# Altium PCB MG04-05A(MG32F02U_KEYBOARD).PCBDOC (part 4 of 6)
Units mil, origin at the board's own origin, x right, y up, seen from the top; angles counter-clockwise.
Board outline 17912.8 x 10422.68 mil, 2 copper layers (Top Layer, Bottom Layer); 623 components, 347 nets, 1816 pads, 821 vias.
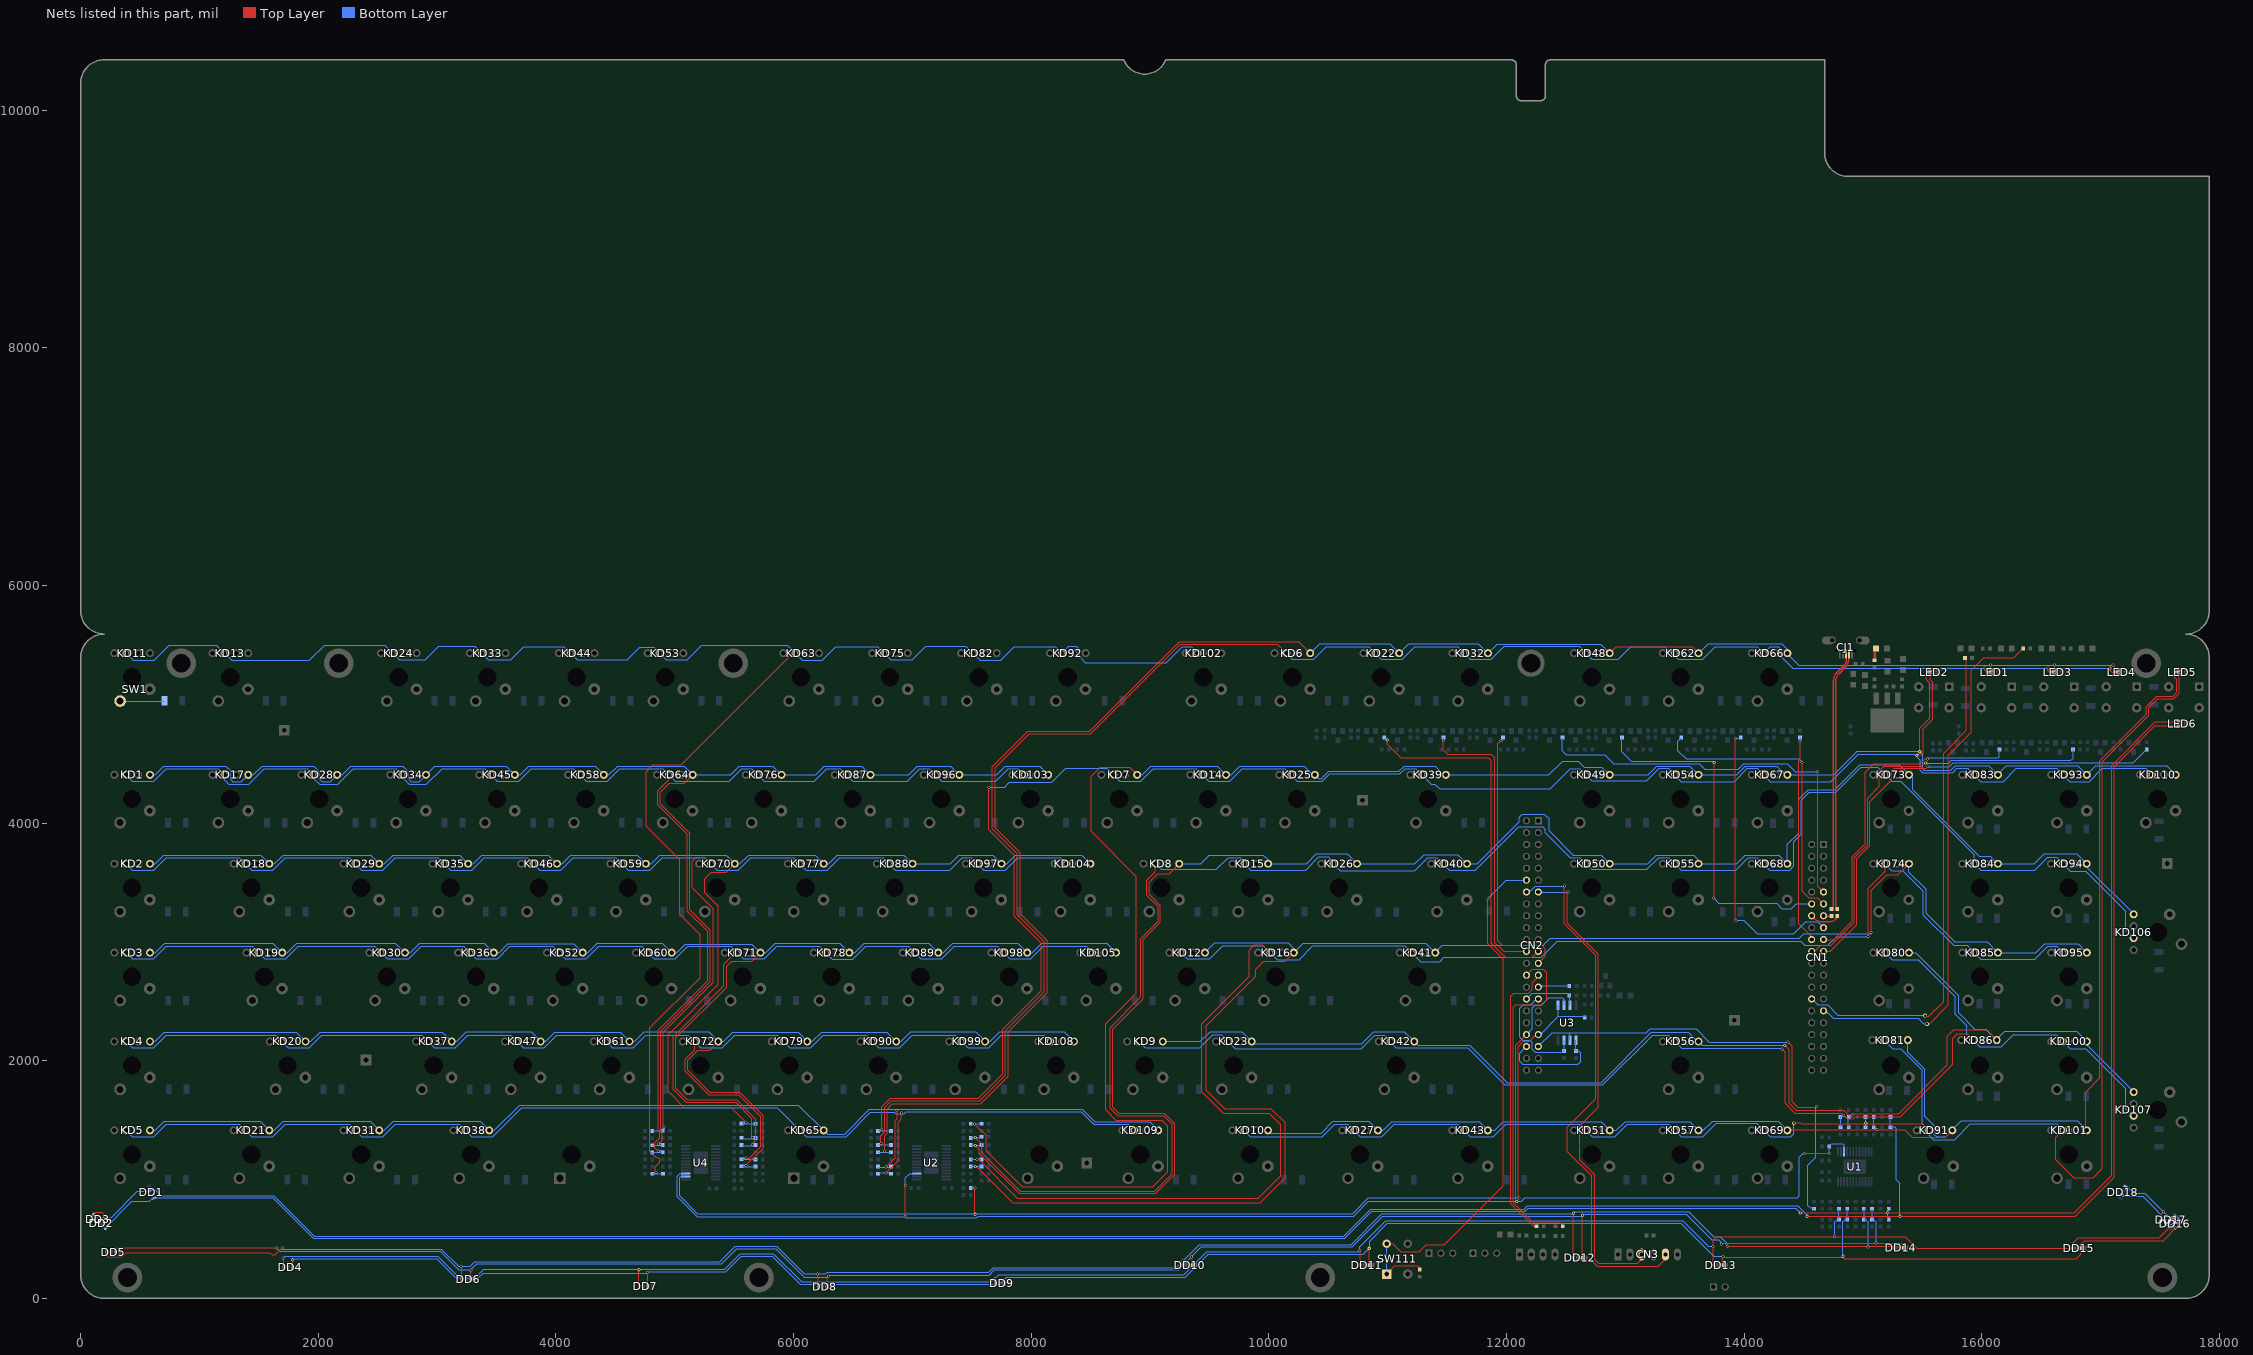
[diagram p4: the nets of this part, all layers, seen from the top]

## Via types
v1: diameter 30, hole 12, Top Layer to Bottom Layer, tented both sides, 273 vias
v2: diameter 26, hole 16, Top Layer to Bottom Layer, tented both sides, 181 vias
v3: diameter 26, hole 12, Top Layer to Bottom Layer, tented both sides, 165 vias
v4: diameter 33, hole 20, Top Layer to Bottom Layer, tented both sides, 61 vias
v5: diameter 25, hole 12, Top Layer to Bottom Layer, tented both sides, 47 vias
v6: diameter 20, hole 12, Top Layer to Bottom Layer, tented both sides, 40 vias
v7: diameter 30, hole 16, Top Layer to Bottom Layer, tented both sides, 30 vias
v8: diameter 28, hole 16, Top Layer to Bottom Layer, tented both sides, 12 vias
v9: diameter 35, hole 20, Top Layer to Bottom Layer, tented both sides, 5 vias
v10: diameter 25, hole 16, Top Layer to Bottom Layer, tented both sides, 3 vias
v11: diameter 40, hole 12, Top Layer to Bottom Layer, tented both sides, 3 vias
v12: diameter 40, hole 20, Top Layer to Bottom Layer, tented both sides, 1 vias

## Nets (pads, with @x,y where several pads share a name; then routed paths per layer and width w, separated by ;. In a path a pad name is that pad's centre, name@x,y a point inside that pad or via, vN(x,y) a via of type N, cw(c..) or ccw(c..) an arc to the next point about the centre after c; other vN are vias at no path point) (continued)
LED_G1: C51.1 KD1.3 KD17.3 KD28.3 KD34.3 KD45.3 KD58.3 KD64.3 KD76.3 KD87.3 KD96.3 KD103.3 R121.1 | length 12173.4
  Top Layer w8: v2(4862.07,1298.92) 4892.57,1329.41 4892.57,1408.92 4882.32,1419.16 4882.32,2249.07 5296.96,2663.71 5296.96,3097.04 5125,3269 5125,3915.41 4878.66,4161.75 4878.66,4261.31 4951.45,4334.1 5078.06,4334.1 KD64.3@5150.17,4406.2
  Bottom Layer w8: KD1.3@583.27,4406.2 627.01,4406.2 699.21,4478.4 1221.77,4478.4 1261.77,4438.4 1261.77,4367.8 1281.77,4347.8 1351.76,4347.8 KD17.3@1410.16,4406.2 1453.9,4406.2 1526.1,4478.4 1961.17,4478.4 2006.77,4432.8 2006.77,4372.8 2031.77,4347.8 2099.64,4347.8 KD28.3@2158.04,4406.2 2201.78,4406.2 2273.98,4478.4 2711.17,4478.4 2756.77,4432.8 2756.77,4372.8 2781.77,4347.8 2847.75,4347.8 KD34.3@2906.15,4406.2 2978.35,4478.4 3581.95,4478.4 KD45.3@3654.14,4406.2 3697.89,4406.2 3770.09,4478.4 4329.98,4478.4 KD58.3@4402.18,4406.2 4445.92,4406.2 4518.12,4478.4 5077.97,4478.4 KD64.3@5150.17,4406.2 5470.2,4406.2 5542.4,4478.4 5826,4478.4 KD76.3@5898.2,4406.2 6185.2,4406.2 6257.4,4478.4 6574.04,4478.4 KD87.3@6646.24,4406.2 6968.2,4406.2 7040.4,4478.4 7322.12,4478.4 KD96.3@7394.31,4406.2 7710.2,4406.2 7782.4,4478.4 8070.11,4478.4 KD103.3@8142.3,4406.2 ; C51.1@4812,1290.31 R121.1@4896,1290.31
  Bottom Layer w12: v2@4867.43,1301.08 R121.1@4887.13,1301.08
LED_G2: C57.1 KD2.3 KD18.3 KD29.3 KD35.3 KD46.3 KD59.3 KD70.3 KD77.3 KD88.3 KD97.3 KD104.3 R126.2 | length 11735.7
  Top Layer w8: KD70.3@5504.58,3657.8 5432.47,3585.7 5305.86,3585.7 5252,3531.84 5252,3414 5366.96,3299.04 5366.96,2643.71 4943.54,2220.29 4943.54,1741.47 5077.28,1607.72 5471.82,1607.72 v2(5598.15,1481.39)
  Bottom Layer w8: KD2.3@583.27,3657.8 627.01,3657.8 699.21,3730 1515.01,3730 KD18.3@1587.21,3657.8 1630.95,3657.8 1703.15,3730 2440.4,3730 KD29.3@2512.6,3657.8 2556.35,3657.8 2628.54,3730 3188.29,3730 KD35.3@3260.48,3657.8 3304.23,3657.8 3376.42,3730 3936.32,3730 KD46.3@4008.51,3657.8 4052.26,3657.8 4124.46,3730 4684.31,3730 KD59.3@4756.51,3657.8 4800.25,3657.8 4872.45,3730 5432.38,3730 KD70.3@5504.58,3657.8 5548.32,3657.8 5620.52,3730 6180.37,3730 KD77.3@6252.57,3657.8 6296.32,3657.8 6368.51,3730 6928.45,3730 KD88.3@7000.64,3657.8 7317.8,3657.8 7390,3730 7676.49,3730 KD97.3@7748.68,3657.8 7792.43,3657.8 7864.63,3730 8424.52,3730 KD104.3@8496.72,3657.8 ; R126.2@5563.58,1471.39 C57.1@5687.58,1471.39
  Bottom Layer w12: R126.2@5572.87,1478.92 v2@5592.57,1478.92
LED_G3: C52.1 KD3.3 KD19.3 KD30.3 KD36.3 KD52.3 KD60.3 KD71.3 KD78.3 KD89.3 KD98.3 KD105.3 R120.2 | length 11446
  Top Layer w8: 5648,2837.4 5648.7,2838.1 ; v2@5648.79,1296.17 5683.15,1330.53 5683.15,1495 ; 5649.01,2838.1 5648.7,2838.1 ; 5683.15,1505 5683.15,1495 ; KD71.3@5720.1,2909.5 5648.7,2838.1 ; 5648.7,2838.1 5478.25,2838.1 5435,2794.85 5435,2620.6 5007.32,2192.92 5007.32,1767.68 5103.64,1671.36 5520.79,1671.36 5683.15,1509 5683.15,1495
  Bottom Layer w8: KD3.3@583.27,2910.2 627.01,2910.2 706.81,2990 1615.68,2990 KD19.3@1695.48,2910.2 1739.22,2910.2 1819.02,2990 2649.14,2990 KD30.3@2728.94,2910.2 2772.69,2910.2 2852.48,2990 3397.22,2990 KD36.3@3477.01,2910.2 3520.76,2910.2 3595.55,2985 4150.25,2985 KD52.3@4225.04,2910.2 4268.79,2910.2 4348.59,2990 4893.29,2990 KD60.3@4973.09,2910.2 5016.83,2910.2 5089.03,2982.4 5648.92,2982.4 KD71.3@5721.12,2910.2 5764.86,2910.2 5844.66,2990 6389.35,2990 KD78.3@6469.15,2910.2 6512.9,2910.2 6592.69,2990 7137.39,2990 KD89.3@7217.18,2910.2 7260.93,2910.2 7340.72,2990 7885.42,2990 KD98.3@7965.21,2910.2 8008.96,2910.2 8088.76,2990 8633.41,2990 KD105.3@8713.21,2910.2 ; R120.2@5563.58,1291.39 5569.97,1285 C52.1@5668.15,1285
  other v2: 5653.15,1295
LED_G4: C45.1 KD4.3 KD20.3 KD37.3 KD47.3 KD61.3 KD72.3 KD79.3 KD90.3 KD99.3 KD108.3 R114.2 | length 10183
  Top Layer w8: KD72.3@5366.76,2162.1 5294.65,2090 5193.79,2090 5109.6,2005.81 5109.6,1918.4 5293,1735 5547.15,1735 5743.15,1539 5743.15,1265 v2(5598.15,1120)
  Bottom Layer w8: KD4.3@583.27,2162.1 627.01,2162.1 704.91,2240 1814.43,2240 KD20.3@1892.33,2162.1 1936.07,2162.1 2014.97,2241 3043.76,2241 KD37.3@3122.65,2162.1 3166.4,2162.1 3246.29,2242 3790.82,2242 KD47.3@3870.71,2162.1 3914.46,2162.1 3991.36,2239 4541.83,2239 KD61.3@4618.73,2162.1 4662.47,2162.1 4742.37,2242 5286.86,2242 KD72.3@5366.76,2162.1 5410.5,2162.1 5488.4,2240 6036.89,2240 KD79.3@6114.79,2162.1 6158.53,2162.1 6236.43,2240 6784.92,2240 KD90.3@6862.82,2162.1 6906.57,2162.1 6986.46,2242 7530.96,2242 KD99.3@7610.85,2162.1 7654.6,2162.1 7734.5,2242 8279,2242 KD108.3@8358.9,2162.1 ; R114.2@5564.97,1110 C45.1@5686.19,1110
  Bottom Layer w12: R114.2@5572.87,1118.92 v2@5592.57,1118.92
LED_G5: C28.1 KD5.3 KD21.3 KD31.3 KD38.3 KD65.3 KD109.3 R91.1 | length 9634.9
  Top Layer w8: v2(6778.24,1106) 6857,1184.76 6857,1493 6874,1510 v2@6874,1579.47
  Bottom Layer w8: KD5.3@583.27,1414.1 627.01,1414.1 702.71,1489.8 1511.52,1489.8 KD21.3@1587.22,1414.1 1630.96,1414.1 1706.66,1489.8 2436.72,1489.8 KD31.3@2512.42,1414.1 2556.17,1414.1 2631.87,1489.8 3361.92,1489.8 KD38.3@3437.62,1414.1 3481.37,1414.1 3694.23,1626.97 6039.73,1626.97 KD65.3@6252.59,1414.1 6285.51,1381.19 6428.19,1381.19 6637,1590 8428.47,1590 8532.17,1486.3 8995.36,1486.3 KD109.3@9067.56,1414.1 ; C28.1@6715,1104.89 R91.1@6815,1104.89
  other v2: 6871,1581.47
LED_G6: C34.1 KD6.3 KD22.3 KD32.3 KD48.3 KD62.3 KD66.3 LED1.3 LED3.3 LED4.3 R97.1 | length 14903.3
  Top Layer w8: v2(6735,1304.89) 6735,1369.89 6767,1401.89 6767,1607.47 6821.25,1661.72 7564.87,1661.72 7782.5,1879.35 7782.5,2254.35 8108.9,2580.75 8108.9,2999.56 7881.75,3226.72 7881.75,3741.72 7670.56,3952.9 7670.56,4475.03 7970.53,4775 8492.99,4775 9245.42,5527.43 10249.45,5527.43 KD6.3@10347.07,5429.8 ; KD48.3@12866.92,5429.8 12921.1,5483.98 13560.62,5483.98 KD62.3@13614.8,5429.8 ; v2(16072,5330) 16072,5290 LED1.3@16075.27,5286.73 ; LED3.3@16605.5,5286.73 16605.27,5286.73 16612,5280 v2(16612,5330) ; v2(17102,5330) 17145.27,5286.73 LED4.3@17145.5,5286.73
  Bottom Layer w8: C34.1@6710,1291.39 R97.1@6812.17,1291.39 ; KD6.3@10347.23,5429.8 10427.43,5510 11015.07,5510 KD22.3@11095.21,5429.86 ; KD22.3@11095.15,5429.8 KD22.3@11095.21,5429.86 ; KD22.3@11095.26,5429.8 KD22.3@11095.21,5429.86 ; KD48.3@12866.92,5429.8 12790.47,5506.25 11919.63,5506.25 KD32.3@11843.18,5429.8 11762.99,5510 11175.35,5510 KD22.3@11095.21,5429.86 ; KD62.3@13614.88,5429.88 13614.96,5429.8 13695.16,5510 14317.15,5510 14362.99,5464.16 KD66.3@14362.99,5429.8 14362.99,5426.01 14459,5330 v2(16072,5330) v2(16612,5330) v2(17102,5330)
LED_G7: C40.1 KD7.3 KD14.3 KD25.3 KD39.3 KD49.3 KD54.3 KD67.3 KD83.3 KD93.3 KD110.3 LED2.3 R106.2 | length 16841.8
  Top Layer w8: v2@7523.1,1466 v2@7525.78,1466 ; v2(7523.29,1468.48) v2@7525.78,1466 ; v2@7530.82,1466 v2@7525.78,1466 ; KD7.3@8890.38,4406.2 8826.58,4470 8578.15,4470 8503.15,4395 8503.15,3930.32 8884.85,3548.62 8884.85,2569.32 8627,2311.47 8627,1585.86 8711.86,1501 9096.85,1501 9150,1447.85 9150,1066.85 9023.63,940.48 7922.6,940.48 7620.29,1242.79 7620.29,1371.48 v2@7525.78,1466 ; v2@15476.85,4610.7 15476.85,4798.48 15562.45,4884.09 15562.45,5175.09 15529.6,5207.95 15529.6,5266.73 LED2.3@15549.6,5286.73
  Bottom Layer w8: R106.2@7489.17,1471.39 C40.1@7573.17,1471.39 ; KD7.3@8890.38,4406.2 8934.12,4406.2 9006.32,4478.4 9566.17,4478.4 ; 9566.25,4478.4 KD14.3@9638.45,4406.2 9682.19,4406.2 9754.39,4478.4 10296.17,4478.4 10368.37,4406.2 KD25.3@10386.44,4406.2 10417.64,4375 10441.15,4375 10501.85,4435.7 11093.85,4435.7 11136.55,4478.4 11400.75,4478.4 11472.95,4406.2 KD39.3@11488.88,4406.2 12355.17,4406.2 12470.43,4521.47 12601.08,4521.47 12651.85,4470.7 12802.27,4470.7 KD49.3@12866.77,4406.2 13190.8,4406.2 13264.6,4480 13541.04,4480 KD54.3@13614.84,4406.2 13936.01,4406.2 14009.81,4480 14273.15,4480 14346.95,4406.2 KD67.3@14362.87,4406.2 14754.35,4406.2 14952.63,4604.48 v2@15476.85,4604.48 ; v2@15481.85,4600.7 v2(15476.85,4600.7) 15501.85,4575.7 15501.85,4455.7 15511.85,4445.7 15736.85,4445.7 15774.64,4483.48 16057.43,4483.48 KD83.3@16134.7,4406.2 16134.7,4411.55 16206.63,4483.48 16805.25,4483.48 KD93.3@16882.53,4406.2 16959.81,4483.48 17553.31,4483.48 KD110.3@17630.59,4406.2
LED_G8: C33.1 KD8.3 KD15.3 KD26.3 KD40.3 KD50.3 KD55.3 KD68.3 KD73.3 KD84.3 KD94.3 KD106.3 R96.2 | length 15517.5
  Top Layer w8: v2@7523.1,1286 v2@7528.29,1286 ; v2(7528.29,1288.48) 7563.29,1253.48 7563.29,1219.18 7898.99,883.48 9047.24,883.48 9207,1043.24 9207,1471.46 9120.46,1558 8735.47,1558 8684,1609.47 8684,2263.47 8941.85,2521.32 8941.85,3020.7 9086.85,3165.7 9086.85,3305.7 8991.85,3400.7 8991.85,3503.7 9063.15,3575 9161.94,3575 KD8.3@9244.75,3657.8
  Bottom Layer w8: R96.2@7489.17,1290 7563.15,1290 ; KD8.3@9244.75,3657.8 9426.8,3657.8 9499,3730 9953.15,3730 9992.78,3690.37 KD15.3@9992.78,3657.8 10317.8,3657.8 10400,3740 10658.61,3740 KD26.3@10740.81,3657.8 11227.8,3657.8 11305,3735 11588.78,3735 KD40.3@11665.97,3657.8 11754.8,3657.8 12107,4010 12107,4050 12132,4075 12317,4075 12357,4035 12357,3935 12562,3730 12794.57,3730 KD50.3@12866.77,3657.8 13188.8,3657.8 13261,3730 13573.15,3730 13614.84,3688.31 KD55.3@13614.84,3657.8 13937.8,3657.8 14010,3730 14290.67,3730 KD68.3@14362.87,3657.8 14362.87,3820.87 14457,3915 14457,4200 14537,4280 14762,4280 14972,4490 15302.66,4490 KD73.3@15386.45,4406.2 15416.85,4375.81 15416.85,4280.7 15976.73,3720.81 16071.51,3720.81 KD84.3@16134.52,3657.8 16441.59,3657.8 16525.25,3741.47 16798.08,3741.47 16807.95,3731.6 ; 16808.55,3731.6 16807.95,3731.6 ; KD94.3@16878.15,3630 KD94.3@16881.75,3630 ; KD106.3@17275.69,3235.07 16881.75,3629.01 KD94.3@16881.75,3630 ; 16807.95,3731.6 KD94.3@16881.75,3657.8 KD94.3@16881.75,3630
LED_G9: C27.1 KD12.3 KD16.3 KD41.3 KD74.3 KD85.3 KD95.3 R89.2 | length 14364.5
  Top Layer w8: v2(7528.29,1111.39) 7538.5,1111.39 7843.29,806.6 9925.98,806.6 10135.15,1015.77 10135.15,1478.61 10016.76,1597 9630,1597 9474,1753 9474,2295.13 9889.6,2710.73 9889.6,2771.45 9956.25,2838.1 10137.22,2838.1 KD16.3@10209.32,2910.2 ; v2@15067,3070 v2(15067,3080) 15067,3435 15197.05,3565.05 15292.91,3565.05 KD74.3@15385.67,3657.8
  Bottom Layer w8: R89.2@7489.17,1111.39 v2(7528.29,1111.39) C27.1@7580,1111.39 ; KD12.3@9461.29,2931.86 KD12.3@9461.29,2910.2 9542.08,2991 10162.15,2991 10209.32,2943.83 KD16.3@10209.32,2910.2 10289.12,2990 11320.47,2990 KD41.3@11400.26,2910.2 11460.06,2970 12307,2970 12367,3030 14462,3030 14502,3070 v2@15067,3070 ; KD74.3@15385.67,3657.8 15385.67,3587.48 15531.77,3441.38 15531.77,3241.38 15773.15,3000 16044.91,3000 KD85.3@16134.7,2910.2 16453.99,2910.2 16527.79,2984 16808.95,2984 KD95.3@16882.75,2910.2
LED_G10: C11.1 KD9.3 KD23.3 KD42.3 KD56.3 KD80.3 KD86.3 KD100.3 KD107.3 R69.1 | length 11162.1
  Top Layer w8: v2(14340.26,2129.31) 14378.04,2091.53 14378.04,1643.74 14436.78,1585 14836.78,1585 14876.78,1545 v2(14905.59,1545) 14915.59,1555 15298.15,1555 15707.91,1964.76 15707.91,2205 15762.91,2260 16038.8,2260 KD86.3@16124.68,2174.11
  Bottom Layer w8: KD9.3@9106.93,2162.1 9423.26,2162.1 9506.15,2245 9772.06,2245 KD23.3@9854.96,2162.1 9872.06,2145 10781.15,2145 10881.85,2245.7 11139.48,2245.7 KD42.3@11223.07,2162.1 11253.71,2131.47 11688.27,2131.47 12003.27,1816.47 12795.47,1816.47 13218,2239 13527.92,2239 13604.82,2162.1 KD56.3@13614.81,2162.1 13646.91,2130 v2@14328.57,2130 ; C11.1@14875,1529.89 14875,1444.89 R69.1@14880,1439.89 ; C11.1@14887,1535 v2@14905,1535 ; KD80.3@15386.03,2910.2 15441.95,2910.2 15803.3,2548.85 15803.3,2403.7 15940.73,2266.27 16032.53,2266.27 KD86.3@16124.68,2174.11 16124.68,2179.47 16193.13,2247.91 16796.73,2247.91 KD100.3@16882.54,2162.1 ; KD100.3@16885.21,2164.78 16882.54,2167.45 KD100.3@16882.54,2162.1 ; KD107.3@17276.48,1736.37 17276.48,1739.37 16882.54,2133.31 KD100.3@16882.54,2162.1
LED_G11: C17.1 KD10.3 KD27.3 KD43.3 KD51.3 KD57.3 KD69.3 KD81.3 KD91.3 KD101.3 LED5.3 R75.1 | length 12825.3
  Top Layer w8: KD69.3@14367.07,1409.89 14375.66,1418.48 15348.52,1418.48 15412,1355 15691.57,1355 KD91.3@15750.67,1414.1 ; KD101.3@16871.85,1415.7 16871.85,1734.4 16993.15,1855.7 16993.15,4525.86 17382,4914.71 17382,4977.45 17473.03,5068.48 17608.03,5068.48 17639.6,5100.05 17639.6,5208.48 17619.6,5228.48 17619.6,5281.73 17624.6,5286.73 LED5.3@17655.5,5286.73 ; KD101.3@16882.72,1408.48 KD101.3@16882.72,1414.1
  Bottom Layer w8: KD10.3@9991.76,1414.1 10015.86,1390 10438.15,1390 10537.95,1489.8 10841.26,1489.8 KD27.3@10916.96,1414.1 10960.71,1414.1 11032.9,1486.3 11769.97,1486.3 KD43.3@11842.16,1414.1 11899.64,1414.1 11971.83,1486.3 12794.58,1486.3 KD51.3@12866.78,1414.1 12924.64,1414.1 12996.83,1486.3 13542.61,1486.3 KD57.3@13614.81,1414.1 13654.64,1414.1 13732.73,1492.2 14284.76,1492.2 KD69.3@14362.85,1414.1 ; R75.1@15090,1439.89 C17.1@15090,1519.89 ; R75.1@15097.09,1437.8 v2@15113.44,1421.44 ; KD81.3@15376.65,2174.11 15376.65,2072.38 15519.6,1929.43 15519.6,1533.48 15599.6,1453.48 15599.6,1378.48 15619.6,1358.48 15695.05,1358.48 KD91.3@15750.67,1414.1 15750.67,1419.45 15824.7,1493.48 16803.34,1493.48 KD101.3@16882.72,1414.1
  other v2: 15115.29,1421.48
LED_G12: C22.1 DD1.3 DD2.3 DD3.3 LED6.3 R80.2 | length 21850.1
  Top Layer w8: DD3.3@104.03,703.12 126.61,725.7 176.85,725.7 v2(256.85,645.7) ; v2@14469,720.47 15222,720.47 ; v2(15207,721.47) 16777.62,721.47 17093.15,1037 17093.15,4484.43 17460.45,4851.73 LED6.3@17655.5,4851.73
  Bottom Layer w8: DD2.3@214.15,593 214.15,599.15 431.69,816.69 579.02,816.69 606.74,844.41 DD1.3@618.79,844.41 DD1.3@619.39,844.41 ; DD1.3@619.39,845 1616.58,845 1956.58,505 10639.05,505 10865.52,731.47 12158.05,731.47 12184,757.41 14434.05,757.41 v2@14471.5,719.97 ; C22.1@15206.35,662.8 R80.2@15206.35,744 ; R80.2@15206.35,752.8 R80.2@15206.35,744 ; R80.2@15213.35,744 R80.2@15206.35,744
  other v2: 14471,719.47
LED_G13: C16.1 DD5.3 DD6.3 DD8.3 DD10.3 DD12.3 DD14.3 R74.2 | length 16853.7
  Top Layer w8: DD5.3@218.03,390.32 218.03,364.52 231.85,350.7 346.85,350.7 381.85,385.7 1591.85,385.7 1611.85,365.7 1636.85,365.7 v2(1696.85,425.7) ; DD6.3@3208.03,160.32 v2@3208.03,267 ; DD8.3@6208.03,100 v2@6208.03,206.47 ; DD10.3@9278.03,280.32 v2@9278.03,313.48 ; DD12.3@12562.03,340.11 DD12.3@12562.03,340.32 v2(12562.03,716.47) ; v2(13858.29,438.48) 14629.6,438.48 ; 14588.93,438.48 14629.6,438.48 ; DD14.3@15261.36,425.32 15248.2,438.48 14629.6,438.48
  Bottom Layer w8: v2@1696.85,415.78 3034.22,415.78 3180,270 3276.53,270 3316.53,310 5379.81,310 5507.81,438 5858.77,438 6090.31,206.47 v2(6202,206.47) 6269.69,206.47 6283.22,220 7641.54,220 7681.54,260 9221.12,260 9414.6,453.48 10690.62,453.48 10948.6,711.47 12557.03,711.47 v2@12560.03,714.47 ; v2@12564,714.47 v2@12560.03,714.47 ; v2(13858.29,438.48) 13858.29,458.48 13798.29,518.48 13741.09,518.48 13532.1,727.47 12573.03,727.47 v2(12562.03,716.47) v2@12560.03,714.47 ; C16.1@15006,663.89 C16.1@15016,663.89 ; R74.2@15006,753.89 15011,748.89 15011,668.89 C16.1@15016,663.89 ; C16.1@15015.41,666.24 C16.1@15016,663.89 ; v2@15041.4,433.95 15041.4,643.08 ; 15041.4,507.48 15041.4,643.08 ; C16.1@15016,663.89 15020.6,663.89 15041.4,643.08
  other v2: 3200,267 9273.29,313.48 15039.93,432.48
LED_G14: C10.1 DD4.3 DD7.3 DD9.3 DD11.3 DD13.3 DD15.3 DD16.3 DD17.3 DD18.3 R68.2 | length 18198.5
  Top Layer w8: DD4.3@1708.03,260.32 v2@1708.03,340.7 ; DD7.3@4698.03,100.42 v2@4698.03,238.48 ; v2@7695,158.47 7695,135 7698.03,131.97 DD9.3@7698.03,125.49 ; DD11.3@10768.03,280.32 v2@10768.03,398.74 ; v2(13738.29,438.48) 13738.29,488.48 13768.29,518.48 15354,518.48 15451.17,421.32 DD15.3@16758.36,421.32 16758.36,459.7 16809.36,510.7 17493.85,510.7 17568.15,585 17568.15,603.05 17507,664.2 17507,710 v2(17527,730) ; DD13.3@13740.03,280.32 v2@13740.03,431.74
  Bottom Layer w8: v2@1708.03,340.7 1721.96,354.63 3005.37,354.63 3167.39,192.61 3337.61,192.61 3392,247 5419.24,247 5549.24,377 5829.96,377 6068.02,138.94 7663.94,138.94 v2(7689.47,164.47) 7725,200 9281.12,200 9474.6,393.48 10683.29,393.48 ; 10723.02,393.48 10683.29,393.48 ; v2(13738.29,438.48) 13696.09,438.48 13483.1,651.47 10981,651.47 10763.29,433.76 v2(10763.29,403.48) 10753.29,393.48 10683.29,393.48 ; v2@14760.6,512.48 14760.6,643.08 14781.4,663.89 C10.1@14796,663.89 R68.2@14796,753.89 ; DD18.3@17210.1,941.31 17221.41,930 17228.47,930 ; DD18.3@17222,936.47 17228.47,930 ; DD16.3@17660.83,666.27 17637.1,690 17567,690 v2(17527,730) 17370.53,886.47 17272,886.47 17228.47,930
  other v2: 4699.6,241.48 1701.85,340.7 14759.93,520.48
LED_PW: CN2.29 R2.1 | length 264.1
  Bottom Layer w8: CN2.29@12267,2620 12277,2630 R2.1@12527,2630
LED_R0: C43.1 KD11.2 KD13.2 KD24.2 KD33.2 KD44.2 KD53.2 KD63.2 KD75.2 KD82.2 KD92.2 KD102.2 R113.1 | length 15669.1
  Top Layer w8: v2(4842.57,1058.92) 4836.85,1064.64 4836.85,1109.2 4873.85,1146.2 4873.85,1171.2 4856.12,1188.92 4841.02,1188.92 4790,1239.94 4790,2275.83 5212.75,2698.59 5212.75,3062.16 5040.8,3234.12 5040.8,3692.12 4757.84,3975.07 4757.84,4434.06 4816,4492.21 5054.21,4492.21 5991.8,5429.8 KD63.2@6013.57,5429.8
  Bottom Layer w8: KD11.2@383.27,5429.8 444.59,5368.48 618.29,5368.48 746.28,5496.47 1142.9,5496.47 KD13.2@1209.57,5429.8 1269.37,5370 1925.53,5370 2052,5496.47 2560.9,5496.47 KD24.2@2627.56,5429.8 2682.36,5375 2898.15,5375 3013.15,5490 3315.37,5490 KD33.2@3375.56,5429.8 3430.37,5375 3618.15,5375 3729.15,5486 4067.37,5486 KD44.2@4123.56,5429.8 4178.37,5375 4599.43,5375 4704.43,5480 4821.37,5480 KD53.2@4871.57,5429.8 4927.89,5373.48 5104.48,5373.48 5227.47,5496.47 5946.91,5496.47 KD63.2@6013.57,5429.8 6073.37,5370 6240,5370 6355,5485 6706.03,5485 KD75.2@6761.23,5429.8 6817.55,5373.48 6996.63,5373.48 7113.15,5490 7449.12,5490 KD82.2@7509.31,5429.8 7570.63,5368.48 7741.48,5368.48 7858,5485 8202.15,5485 KD92.2@8257.35,5429.8 8313.79,5486.25 8379.6,5486.25 8407.35,5458.5 8407.35,5399.8 8455.69,5351.46 9136.32,5351.46 9269.87,5485 9343.96,5485 KD102.2@9399.16,5429.8 ; C43.1@4820,1055 v2@4841.96,1055 ; C43.1@4820.61,1058.92 4812,1050.31 R113.1@4896,1050.31
LED_R1: C50.1 KD1.2 KD17.2 KD28.2 KD34.2 KD45.2 KD58.2 KD64.2 KD76.2 KD87.2 KD96.2 KD103.2 R119.1 | length 12235.2
  Top Layer w8: v2(4862.07,1238.92) 4832.57,1268.42 4832.57,1310.07 4872.57,1350.07 4872.57,1398.92 4861.11,1410.37 4861.11,2257.86 5275.75,2672.5 5275.75,3088.25 5103.79,3260.21 5103.79,3906.63 4857.45,4152.96 4857.45,4270.1 4950.17,4362.82 KD64.2@4950.17,4406.2
  Bottom Layer w8: KD1.2@383.27,4406.2 436.07,4353.4 614.21,4353.4 719.21,4458.4 1157.96,4458.4 KD17.2@1210.16,4406.2 1210.16,4364.41 1246.77,4327.8 1415.5,4327.8 1546.1,4458.4 1905.84,4458.4 KD28.2@1958.04,4406.2 1958.04,4378.74 2010.29,4326.48 2162.06,4326.48 2293.98,4458.4 2653.95,4458.4 KD34.2@2706.15,4406.2 2706.15,4385.62 2765.29,4326.48 2910.18,4326.48 3042.09,4458.4 3401.95,4458.4 KD45.2@3454.14,4406.2 3506.95,4353.4 3685.09,4353.4 3790.09,4458.4 4149.98,4458.4 KD58.2@4202.18,4406.2 4254.98,4353.4 4433.12,4353.4 4538.12,4458.4 4897.97,4458.4 KD64.2@4950.17,4406.2 5002.97,4353.4 5457.4,4353.4 5562.4,4458.4 5646,4458.4 KD76.2@5698.2,4406.2 5751,4353.4 6172.4,4353.4 6277.4,4458.4 6394.04,4458.4 KD87.2@6446.24,4406.2 6499.04,4353.4 6955.4,4353.4 7060.4,4458.4 7142.12,4458.4 KD96.2@7194.31,4406.2 7247.12,4353.4 7701.4,4353.4 7806.4,4458.4 7890.11,4458.4 KD103.2@7942.3,4406.2 ; C50.1@4812,1230.31 R119.1@4896,1230.31
  Bottom Layer w12: v2@4867.43,1241.08 R119.1@4887.13,1241.08
LED_R2: C55.1 KD2.2 KD18.2 KD29.2 KD35.2 KD46.2 KD59.2 KD70.2 KD77.2 KD88.2 KD97.2 KD104.2 R125.1 | length 11590.2
  Top Layer w8: v2(4910.57,1440.92) 4901.11,1450.37 4901.11,2237.86 5321.96,2658.71 5321.96,3280.4 5147,3455.36 5147,3678.85 5179.95,3711.8 5250.58,3711.8 KD70.2@5304.58,3657.8
  Bottom Layer w8: KD2.2@383.27,3657.8 436.07,3605 614.21,3605 719.21,3710 1335.01,3710 KD18.2@1387.21,3657.8 1440.01,3605 1618.15,3605 1723.15,3710 2260.4,3710 KD29.2@2312.6,3657.8 2365.4,3605 2543.54,3605 2648.54,3710 3008.29,3710 KD35.2@3060.48,3657.8 3113.29,3605 3291.42,3605 3396.42,3710 3756.32,3710 KD46.2@3808.51,3657.8 3861.32,3605 4039.46,3605 4144.46,3710 4504.31,3710 KD59.2@4556.51,3657.8 4609.31,3605 4787.45,3605 4892.45,3710 5252.38,3710 KD70.2@5304.58,3657.8 5357.38,3605 5535.52,3605 5640.52,3710 6000.37,3710 KD77.2@6052.57,3657.8 6105.37,3605 6283.51,3605 6388.51,3710 6748.45,3710 KD88.2@6800.64,3657.8 6853.45,3605 7312,3605 7417,3710 7496.49,3710 KD97.2@7548.68,3657.8 7601.49,3605 7779.63,3605 7884.63,3710 8244.52,3710 KD104.2@8296.72,3657.8 ; C55.1@4812,1410.31 R125.1@4896,1410.31 ; R125.1@4902.57,1416.87 v2@4902.57,1437.87
  Bottom Layer w12: R125.1@4909.48,1423.35 v2@4909.48,1443.04
LED_R3: C53.1 KD3.2 KD19.2 KD30.2 KD36.2 KD52.2 KD60.2 KD71.2 KD78.2 KD89.2 KD98.2 KD105.2 R122.2 | length 11459.3
  Top Layer w8: KD60.2@4773.09,2910.2 KD60.2@4773.09,2921.91 ; KD71.2@5521.12,2910.2 5510.35,2910.2 5413.79,2813.64 5413.79,2629.39 4986.11,2201.71 4986.11,1758.89 5094.85,1650.15 5512,1650.15 5648.15,1514 5648.15,1485 ; 5648.15,1500 5648.15,1485 ; v2@5648.79,1356.17 5648.15,1356.81 5648.15,1485
  Bottom Layer w8: KD3.2@383.27,2910.2 436.07,2857.4 614.21,2857.4 719.21,2962.4 1443.28,2962.4 KD19.2@1495.48,2910.2 1548.28,2857.4 1726.42,2857.4 1831.42,2962.4 2476.74,2962.4 KD30.2@2528.94,2910.2 2581.74,2857.4 2759.88,2857.4 2864.88,2962.4 3224.82,2962.4 KD36.2@3277.01,2910.2 3329.82,2857.4 3507.95,2857.4 3612.95,2962.4 3972.85,2962.4 KD52.2@4025.04,2910.2 4077.85,2857.4 4255.99,2857.4 4360.99,2962.4 4720.89,2962.4 KD60.2@4773.09,2910.2 4825.89,2857.4 5004.03,2857.4 5109.03,2962.4 5468.92,2962.4 KD71.2@5521.12,2910.2 5573.92,2857.4 5752.06,2857.4 5857.06,2962.4 6216.95,2962.4 KD78.2@6269.15,2910.2 6324.35,2855 6497.69,2855 6605.09,2962.4 6964.99,2962.4 KD89.2@7017.18,2910.2 7069.99,2857.4 7248.12,2857.4 7353.12,2962.4 7713.02,2962.4 KD98.2@7765.21,2910.2 7818.02,2857.4 7996.16,2857.4 8101.16,2962.4 8461.01,2962.4 KD105.2@8513.21,2910.2 ; 5578.15,1345 C53.1@5668.15,1345 ; v2@5648.15,1350 5649.54,1351.39 C53.1@5687.58,1351.39
  other v2: 5653.15,1355
LED_R4: C47.1 KD4.2 KD20.2 KD37.2 KD47.2 KD61.2 KD72.2 KD79.2 KD90.2 KD99.2 KD108.2 R116.2 | length 10229.4
  Top Layer w8: KD72.2@5166.76,2162.1 5166.76,2092.97 5088.39,2014.6 5088.39,1910.61 5285.21,1713.79 5538.36,1713.79 5723.15,1529 5723.15,1275 5628.15,1180 v2(5598.15,1180)
  Bottom Layer w8: KD4.2@383.27,2162.1 436.07,2109.3 614.21,2109.3 719.21,2214.3 1640.13,2214.3 KD20.2@1692.33,2162.1 1745.13,2109.3 1923.27,2109.3 2028.27,2214.3 2870.46,2214.3 KD37.2@2922.65,2162.1 2975.46,2109.3 3153.59,2109.3 3258.59,2214.3 3617.45,2214.3 ; 3618.52,2214.3 KD47.2@3670.71,2162.1 3723.52,2109.3 3901.66,2109.3 4006.66,2214.3 4366.53,2214.3 KD61.2@4418.73,2162.1 4471.53,2109.3 4649.67,2109.3 4754.67,2214.3 5114.56,2214.3 KD72.2@5166.76,2162.1 5219.56,2109.3 5397.7,2109.3 5502.7,2214.3 5862.59,2214.3 KD79.2@5914.79,2162.1 5967.59,2109.3 6145.73,2109.3 6250.73,2214.3 6610.62,2214.3 KD90.2@6662.82,2162.1 6715.62,2109.3 6893.76,2109.3 6998.76,2214.3 7358.66,2214.3 KD99.2@7410.85,2162.1 7463.66,2109.3 7641.8,2109.3 7746.8,2214.3 8106.7,2214.3 KD108.2@8158.9,2162.1 ; R116.2@5563.58,1171.39 C47.1@5687.58,1171.39 ; R116.2@5564.97,1170 v2@5598.15,1170
  Bottom Layer w12: 5577.87,1178.92 v2@5597.57,1178.92
LED_R5: C26.1 KD5.2 KD21.2 KD31.2 KD38.2 KD65.2 KD109.2 R88.1 | length 9778.1
  Top Layer w8: v2(6778.24,1056) 6882,1159.76 6882,1483 6907,1508 v2(6907,1561.47)
  Bottom Layer w8: KD5.2@383.27,1414.1 436.07,1361.3 614.21,1361.3 719.21,1466.3 1335.02,1466.3 KD21.2@1387.22,1414.1 1440.02,1361.3 1618.16,1361.3 1723.16,1466.3 2260.22,1466.3 KD31.2@2312.42,1414.1 2365.22,1361.3 2543.36,1361.3 2648.36,1466.3 3185.43,1466.3 KD38.2@3237.62,1414.1 3290.43,1361.3 3468.56,1361.3 3712.95,1605.69 5861.01,1605.69 KD65.2@6052.59,1414.1 6105.39,1361.3 6441.17,1361.3 6646.33,1566.47 6847,1566.47 6861,1552.47 6930.47,1552.47 6948,1570 8420.18,1570 8523.88,1466.3 8815.36,1466.3 KD109.2@8867.56,1414.1 ; C26.1@6716.11,1056 v2(6778.24,1056) 6803.24,1056
LED_R6: C32.1 KD6.2 KD22.2 KD32.2 KD48.2 KD62.2 KD66.2 LED1.2 LED3.2 LED4.2 R95.1 | length 15192.3
  Top Layer w8: v2@6765,1231.39 v2(6765,1239.28) 6765,1369.89 6787,1391.89 6787,1593.47 6830.5,1636.97 7575.12,1636.97 7807.25,1869.1 7807.25,2244.1 8133.65,2570.5 8133.65,3009.81 7906.5,3236.97 7906.5,3751.97 7698.15,3960.32 7698.15,4467.46 7984.48,4753.79 8501.94,4753.79 9254.36,5506.21 10070.66,5506.21 KD6.2@10147.07,5429.8 ; v2@16027,5302.8 16027,5282.8 16056.53,5253.27 LED1.2@16075.5,5253.27 ; v2@16557,5302.8 16557,5278.27 16582,5253.27 LED3.2@16605.5,5253.27 ; v2(17077,5302.8) 17077,5290.14 17113.87,5253.27 LED4.2@17145.5,5253.27
  Bottom Layer w8: C32.1@6710,1231.39 R95.1@6812.17,1231.39 ; KD6.2@10147.23,5429.8 10197.03,5380 10377,5380 10482,5485 10840.07,5485 KD22.2@10895.26,5429.8 ; KD22.2@10895.15,5429.8 10944.96,5380 11122,5380 11227,5485 11587.99,5485 KD32.2@11643.18,5429.8 11692.99,5380 11872,5380 11978.25,5486.25 12610.47,5486.25 KD48.2@12666.92,5429.8 ; KD48.2@12666.92,5429.8 12716.73,5380 12940.76,5380 13045.76,5485 13332.71,5485 13397.85,5419.86 13404.85,5419.86 13444.71,5380 13652,5380 13757,5485 14107.79,5485 KD66.2@14162.99,5429.8 14217.99,5484.8 14287.35,5484.8 14312.99,5459.16 14312.99,5399.36 14332.35,5380 14332.35,5379.8 14409.35,5302.8 15927.33,5302.8 v2(17077,5302.8)
  other v2: 16027,5305 16557,5305
LED_R7: C39.1 KD7.2 KD14.2 KD25.2 KD39.2 KD49.2 KD54.2 KD67.2 KD83.2 KD93.2 KD110.2 LED2.2 R105.1 | length 15882.9
  Top Layer w8: v2(6740,1419.89) 6740,1614.47 6812,1686.47 7554.62,1686.47 7757.75,1889.6 7757.75,2264.6 8084.16,2591.01 8084.16,2989.31 7857,3216.47 7857,3731.47 7643.15,3945.32 v2(7643.15,4298.48) v2@7643.15,4307.4 ; v2@15454.35,4573.2 15493.01,4573.2 15506.85,4587.04 15506.85,4795.7 15585.64,4874.48 15585.64,5186.91 15565.5,5207.04 LED2.2@15565.5,5253.27
  Bottom Layer w8: C39.1@6710,1411.39 R105.1@6812.17,1411.39 ; v2(7643.15,4298.48) 7648.15,4303.48 7775.42,4303.48 7815.42,4343.48 8170.48,4343.48 8288.21,4461.21 8635.37,4461.21 KD7.2@8690.38,4406.2 8743.18,4353.4 8921.32,4353.4 9026.32,4458.4 9386.17,4458.4 ; 9386.25,4458.4 KD14.2@9438.45,4406.2 9491.25,4353.4 9669.39,4353.4 9774.39,4458.4 10134.24,4458.4 KD25.2@10186.44,4406.2 10239.24,4353.4 10450.1,4353.4 10511.18,4414.48 11102.63,4414.48 11146.55,4458.4 11236.69,4458.4 KD39.2@11288.88,4406.2 11367.28,4327.8 11396.77,4327.8 11436.77,4287.8 12366.77,4287.8 12535.43,4456.47 12616.5,4456.47 KD49.2@12666.77,4406.2 12717.97,4355 13178.15,4355 13283.15,4460 13361.04,4460 KD54.2@13414.84,4406.2 13471.04,4350 13914.81,4350 14024.81,4460 14109.07,4460 KD67.2@14162.87,4406.2 14219.07,4350 14728.15,4350 14958.85,4580.7 15431.85,4580.7 15481.85,4530.7 15481.85,4445.7 15501.85,4425.7 15752.98,4425.7 15787.28,4460 15826.85,4460 ; 15801.15,4460 15826.85,4460 ; KD110.2@17430.59,4406.2 17376.79,4460 17013.15,4460 16903.15,4350 16738.73,4350 KD93.2@16682.53,4406.2 16628.73,4460 16288.79,4460 16178.79,4350 15990.91,4350 KD83.2@15934.7,4406.2 15880.91,4460 15826.85,4460
  Bottom Layer w12: C39.1@6717.87,1418.92 v2@6737.57,1418.92
  other v2: 15451.85,4570.7
LED_R8: C35.1 KD8.2 KD15.2 KD26.2 KD40.2 KD50.2 KD55.2 KD68.2 KD73.2 KD84.2 KD94.2 KD106.2 R98.2 | length 15962.9
  Top Layer w8: v2(7528.29,1353.48) 7582.29,1299.48 7582.29,1227.05 7906.86,902.48 9039.37,902.48 9188,1051.11 9188,1463.59 9112.59,1539 8727.6,1539 8665,1601.6 8665,2279.47 8922.85,2537.32 8922.85,3028.57 9067.85,3173.57 9067.85,3297.83 8972.85,3392.83 8972.85,3519.7 9044.75,3591.6 KD8.2@9044.75,3657.8
  Bottom Layer w8: R98.2@7489.17,1351.39 C35.1@7573.17,1351.39 ; KD8.2@9044.75,3657.8 9092.55,3610 9556,3610 9656,3710 9763.15,3710 9792.78,3680.37 KD15.2@9792.78,3657.8 9845.58,3605 10309,3605 10419,3715 10498,3715 10540.81,3672.19 KD26.2@10540.81,3657.8 10598.61,3600 11226,3600 11336,3710 11413.78,3710 KD40.2@11465.97,3657.8 11518.78,3605 11737,3605 12102,3970 12302,3970 12327,3945 12327,3920 12537,3710 12614.57,3710 KD50.2@12666.77,3657.8 12714.57,3610 13181,3610 13281,3710 13362.64,3710 KD55.2@13414.84,3657.8 13467.64,3605 13929,3605 14034,3710 14110.67,3710 KD68.2@14162.87,3657.8 14215.67,3605 14382,3605 14417,3640 14417,3845 14478.21,3906.21 14478.21,4191.21 14545.79,4258.79 14770.79,4258.79 14980.79,4468.79 ; 15052,4468.79 14980.79,4468.79 ; KD94.2@16682.35,3657.8 16628.55,3711.6 16627.95,3711.6 ; KD106.2@17276.68,3032.43 17208.81,3100.31 17208.81,3259.52 16872.63,3595.7 16743.85,3595.7 KD94.2@16681.75,3657.8 16627.95,3711.6 ; 14980.79,4468.79 15123.87,4468.79 KD73.2@15186.45,4406.2 15241.96,4350.7 15316.85,4350.7 15934.52,3733.02 KD84.2@15934.52,3657.8 15990.73,3601.6 16442.97,3601.6 16552.97,3711.6 16627.95,3711.6
LED_R9: C29.1 KD12.2 KD16.2 KD41.2 KD74.2 KD85.2 KD95.2 R92.2 | length 14435.6
  Top Layer w8: v2(7543.29,1169.89) 7557.6,1169.89 7882.88,844.6 9910.24,844.6 10097.15,1031.51 10097.15,1462.87 10001.02,1559 9614.26,1559 9436,1737.26 9436,2310.87 9834.6,2709.47 9834.6,2931.45 9878.15,2975 9944.52,2975 KD16.2@10009.32,2910.2 ; v2(15042,3045) 15042,3450 15185.67,3593.67 KD74.2@15185.67,3657.8
  Bottom Layer w8: R92.2@7489.17,1180 R92.2@7490,1180 ; R92.2@7490,1169.89 v2(7543.29,1169.89) C29.1@7573.15,1169.89 ; KD12.2@9261.29,2910.2 9311.49,2860 9503.15,2860 9610.15,2967 9952.52,2967 KD16.2@10009.32,2910.2 10069.52,2850 10253.15,2850 10370.15,2967 11143.47,2967 KD41.2@11200.26,2910.2 11275.47,2835 11435.53,2835 11470.53,2870 12293,2870 12428,3005 14474,3005 14509,2970 14702,2970 14777,3045 v2(15042,3045) ; KD74.2@15185.67,3657.8 15242.78,3600.7 15332.45,3600.7 15506.77,3426.38 15506.77,3226.38 15763.15,2970 15874.91,2970 KD85.2@15934.7,2910.2 15990.91,2854 16443.15,2854 16553.15,2964 16628.73,2964 KD95.2@16682.53,2910.2
LED_R10: C8.1 KD9.2 KD23.2 KD42.2 KD56.2 KD80.2 KD86.2 KD100.2 KD107.2 R67.1 | length 11620.8
  Top Layer w8: KD23.2@9659.46,2157.6 KD23.2@9663.96,2162.1 ; v2@14318.26,2098.05 14344.68,2071.63 14344.68,1642.09 14426.78,1560 14818.74,1560 14865.26,1513.48 14915.19,1513.48 14931.7,1530 15313.15,1530 15753.15,1970 15753.15,2190 15791.06,2227.91 15870.89,2227.91 KD86.2@15924.68,2174.11
  Bottom Layer w8: KD9.2@8906.93,2162.1 8959.03,2110 9416.15,2110 9526.15,2220 9597.06,2220 KD23.2@9654.96,2162.1 9717.06,2100 10776.15,2100 10892.15,2216 10969.18,2216 KD42.2@11023.07,2162.1 ; KD42.2@11013.15,2162.1 11067.25,2108 11671.74,2108 11982.97,1796.77 12809.77,1796.77 13229,2216 13360.91,2216 KD56.2@13414.81,2162.1 13471.91,2105 14311.31,2105 v2@14318.26,2098.05 ; v2@14313.26,2093.05 v2@14315.26,2091.05 ; C8.1@14808.15,1535 v2@14834.3,1535 ; R67.1@14810,1439.89 C8.1@14810,1523.89 ; KD80.2@15186.03,2910.2 15246.23,2850 15462.15,2850 15775.01,2537.14 15775.01,2391.99 15870.89,2296.11 15870.89,2227.91 KD86.2@15924.68,2174.11 15980.89,2117.91 16163.15,2117.91 16265.24,2220 16626.62,2220 KD100.2@16672.51,2174.11 ; KD100.2@16682.54,2162.1 16744.64,2100 16873.42,2100 17209.6,1763.82 17209.6,1596.25 17269.48,1536.37 KD107.2@17276.48,1536.37
  Bottom Layer w12: C8.1@14817.87,1533.92 v2@14837.57,1533.92
  other v2: 14833.74,1540 14318.26,2099.05
LED_R11: C14.1 KD10.2 KD27.2 KD43.2 KD51.2 KD57.2 KD69.2 KD81.2 KD91.2 KD101.2 LED5.2 R73.1 | length 14026.5
  Top Layer w8: v8(14417,1475) 14422,1480 14472,1480 14482,1470 15494.78,1470 KD91.2@15550.67,1414.1 15499.78,1465 ; KD101.2@16682.72,1414.1 16623.15,1354.54 16623.15,1165 16770.83,1017.32 16825.83,1017.32 16935.47,1017.32 17013.15,1095 17013.15,4517.57 17402,4906.42 17402,4969.17 17481.32,5048.48 17616.32,5048.48 17659.6,5091.77 17659.6,5168.48 ; 17659.6,5183.48 17659.6,5168.48 ; LED5.2@17659.6,5249.17 17659.6,5168.48
  Bottom Layer w8: KD10.2@9791.76,1414.1 9844.56,1361.3 10449.45,1361.3 10554.45,1466.3 10664.77,1466.3 KD27.2@10716.96,1414.1 10769.77,1361.3 10947.9,1361.3 11052.9,1466.3 11589.97,1466.3 KD43.2@11642.16,1414.1 11694.97,1361.3 11886.83,1361.3 11991.83,1466.3 12614.58,1466.3 KD51.2@12666.78,1414.1 12719.58,1361.3 12911.83,1361.3 13016.83,1466.3 13362.61,1466.3 KD57.2@13414.81,1414.1 13467.61,1361.3 13651.83,1361.3 13762.73,1472.2 14104.76,1472.2 KD69.2@14162.85,1414.1 14216.95,1360 14372,1360 ; 14342,1360 14372,1360 ; v8(14417,1475) 14417,1385 14392,1360 14372,1360 ; C14.1@15020,1519.89 C14.1@15020,1525 ; R73.1@15022,1439.89 v2(15022,1475.89) C14.1@15022,1519.89 ; C14.1@15027,1519.89 C14.1@15027,1520 ; KD81.2@15176.65,2174.11 15250.77,2100 15315.41,2100 15495.83,1919.58 15495.83,1468.95 KD91.2@15550.67,1414.1 15550.67,1377.41 15591.7,1336.38 15771.63,1336.38 15903.15,1467.9 16628.92,1467.9 KD101.2@16682.72,1414.1
LED_R12: C21.1 DD1.2 DD2.2 DD3.2 LED6.2 R79.1 | length 22563.3
  Top Layer w8: DD3.2@157.15,650 162.99,650 v2@185.27,672.28 ; v2(14529,691.47) v2(15309,691.47) 16783.32,691.47 17113.15,1021.3 17113.15,4476.15 17455.27,4818.27 LED6.2@17655.5,4818.27
  Bottom Layer w8: DD2.2@161.03,646.12 167.27,646.12 v2(191.85,670.7) 201.85,680.7 256.85,680.7 477.41,901.26 575.82,901.26 DD1.2@587.05,912.49 589.56,915 628.15,915 678.15,865 1624.87,865 1964.87,525 10630.77,525 10857.23,751.47 12147,751.47 12174,778.47 14450,778.47 v2@14537,691.47 ; R79.1@15230,1439.89 C21.1@15230,1519.89 ; R79.1@15233.15,1443 15265.15,1443 15278.15,1430 15278.15,998.48 15308.15,968.48 v2@15308.15,696.47
LED_R13: C19.1 DD5.2 DD6.2 DD8.2 DD10.2 DD12.2 DD14.2 R76.2 | length 16680.2
  Top Layer w8: DD5.2@293.15,390.32 293.15,422 296.85,425.7 v2(1651.85,425.7) ; DD6.2@3283.15,160.32 v2(3283.15,240) ; DD8.2@6283.15,100 v2@6283.15,188.28 ; DD10.2@9353.15,280.32 v2@9353.15,350.78 ; DD12.2@12637.15,340.11 DD12.2@12637.15,340.32 v2@12637.15,708.48 ; v2(13808.29,458.48) 13813.29,463.48 14639.6,463.48 ; 14588.93,463.48 14639.6,463.48 ; DD14.2@15335.6,425 DD14.2@15335.6,425.32 ; DD14.2@15336.48,425.32 15336.48,445.93 15318.93,463.48 14639.6,463.48
  Bottom Layer w8: v2@1651.85,420.7 1677.55,395 3025,395 3180,240 v2(3283.15,240) 3333.15,290 5394.81,290 5522.81,418 5848.78,418 6087.83,178.94 6283.09,178.94 v2(6292.43,188.28) 6300.61,196.47 7646.29,196.47 7689.83,240 9241.12,240 v2(9349.6,348.48) ; v2@9347.31,350.77 9430.02,433.48 10700.01,433.48 10957.99,691.47 12626.6,691.47 v2@12639.6,704.47 ; v2@12647,706.47 13513.1,706.47 13726.09,493.48 13783.29,493.48 13808.29,468.48 v2(13808.29,458.48) ; R76.2@15076,753.89 C19.1@15076,663.89 15090.6,663.89 15111.4,643.08 15111.4,562.48 ; v2@15111.4,458.95 15111.4,562.48 ; 15111.4,532.48 15111.4,562.48
  other v2: 15109.93,465.48 12637.6,699.47
LED_R14: C12.1 DD4.2 DD7.2 DD9.2 DD11.2 DD13.2 DD15.2 DD16.2 DD17.2 DD18.2 R70.2 | length 18396.2
  Top Layer w8: DD4.2@1783.15,260.32 v2(1783.15,325) ; DD7.2@4773.15,100.42 v2@4773.15,218.48 ; DD9.2@7773.15,125.49 v2(7773.15,159) ; DD11.2@10843.15,280.32 v2@10843.15,422.47 ; DD13.2@13819.48,280.32 v2@13819.48,345 ; v2(13819.48,353.48) v2@13819.48,345 ; 16833.48,446 DD15.2@16833.48,421.32 ; DD17.2@17604.15,676 17648.15,632 17648.15,610 17523.85,485.7 16864.36,485.7 16833.48,454.82 DD15.2@16833.48,421.32 ; v2@13819.48,345 14829.93,345 14841.45,333.48 16793.29,333.48 16833.48,373.67 DD15.2@16833.48,421.32
  Bottom Layer w8: v2@1792,333.85 2996.15,333.85 3157.39,172.61 3347.27,172.61 3388.14,213.48 4759.6,213.48 4769.6,223.48 5428.98,223.48 5558.98,353.48 5820.22,353.48 6054.76,118.94 7733.09,118.94 v2(7773.15,159) 7794.15,180 9296.12,180 9489.6,373.48 10795.02,373.48 v2(10844,422.47) ; v2@10848.29,422.47 10848.29,482.76 10997,631.47 13466.08,631.47 13744.06,353.48 v2(13819.48,353.48) ; v2@14830.6,348.15 14830.6,643.08 ; 14830.6,422.48 14830.6,643.08 ; R70.2@14866,753.89 C12.1@14866,663.89 14851.4,663.89 14830.6,643.08 ; DD18.2@17178.35,873.23 DD18.2@17186.75,873.23 ; DD18.2@17187,857.98 17202,857.98 ; DD18.2@17189.92,873.23 DD18.2@17186.75,873.23 ; v2(17630.52,594.24) 17626.63,594.24 DD16.2@17607.71,613.15 17599.4,613.15 17354.56,857.98 17202,857.98 ; DD18.2@17186.75,873.23 17202,857.98
  other v2: 4769.6,218.48 14829.93,354.48
LED_Y0: CN2.24 R8.1 | length 2414.9
  Top Layer w8: v2(11468,4694) 11468,4615.41 11502.71,4580.7 11869.59,4580.7 11902,4548.28 11902,2993 11975,2920 CN2.24@12167,2920
  Bottom Layer w12: v2(11468,4694) R8.1@11468,4718
LED_Y1: CN2.25 R13.1 | length 2292.7
  Top Layer w8: v2(11952,4694) 11927,4669 11927,3008 11965,2970 12297,2970 12327,2940 12327,2880 CN2.25@12267,2820
  Bottom Layer w12: v2@11953.5,4693.5 R13.1@11970,4710
LED_Y2: CN1.9 R18.1 | length 3476.1
  Top Layer w8: v2(14617,4435) 14617,3470 CN1.9@14667,3420
  Bottom Layer w8: R18.1@12460,4710 R18.1@12470,4720 12470,4608.08 12501.6,4576.48 12680,4576.48 ; 12624.6,4576.48 12680,4576.48 ; v2(14617,4435) 14614.48,4432.48 14430.6,4432.48 14363.6,4499.48 13994.29,4499.48 13948.29,4453.48 13667.6,4453.48 13621.6,4499.48 12901.85,4499.48 12824.85,4576.48 12680,4576.48
LED_Y3: CN1.12 R23.1 | length 2949
  Top Layer w8: v2@13747,3370 v2(13747,4510)
  Bottom Layer w8: R23.1@12970,4720 12970,4600 13050,4520 v2@13747,4520 ; v2(13742,3370) 13787,3325 14272,3325 14317,3280 14397,3280 14437,3320 CN1.12@14567,3320
LED_Y4: CN1.11 R28.1 | length 2517.7
  Top Layer w8: v2@14488.29,4511 14488.29,3427.38 14542.87,3372.8 14614.2,3372.8 CN1.11@14667,3320
  Bottom Layer w8: R28.1@13470,4720 13440,4690 13440,4610 13510,4540 14456.67,4540 14486.29,4510.37 v2@14487.24,4510.37
  other v2: 14486.29,4511
LED_Y5: CN1.15 R33.1 | length 2431.3
  Top Layer w8: v2@13924.6,3180.7 v2(13924.6,4713.48)
  Bottom Layer w8: v2@13924.6,3180.7 v2(13931.85,3180.7) 13996.85,3180.7 14107.55,3070 14417,3070 14517,3170 14617,3170 CN1.15@14667,3120 ; v2(13924.6,4713.48) 13963.48,4713.48 R33.1@13970,4720
LED_Y6: CN1.18 R38.1 | length 1749.9
  Top Layer w8: v2(14470,4685) 14470,4536.47 14458.29,4524.76 14458.29,3153.48 14567,3044.77 CN1.18@14567,3020
  Bottom Layer w12: v2(14470,4685) R38.1@14470,4720
LED_Y7: CN1.17 R43.1 | length 2895.4
  Top Layer w8: CN1.17@14667,3020 14752,3020 14907,3175 14907,3716.57 15017,3826.57 15017,4428.94 15088.76,4500.7 15481.85,4500.7 15521.85,4540.7 v2(15541.85,4540.7)
  Bottom Layer w8: v2@15536.85,4545.7 15539.64,4548.48 16031,4548.48 ; 16075.48,4548.48 16031,4548.48 ; R43.1@16147,4620 16147,4560 16135.48,4548.48 16031,4548.48
LED_Y8: CN1.20 R48.1 | length 3560.4
  Top Layer w8: CN1.20@14567,2920 14592,2920 14642,2970 14732,2970 14927,3165 14927,3708.28 15037,3818.28 15037,4210.85 15136.85,4310.7 15136.85,4440.7 15176.15,4480 15491.15,4480 15511.85,4500.7 v2@15526.85,4500.7
  Bottom Layer w8: v2@15536.85,4505.7 15721.85,4505.7 15743.64,4527.48 16749.48,4527.48 16767,4545 R48.1@16767,4620
  other v2: 15526.85,4505.7
LED_Y9: CN1.19 R53.1 | length 4015
  Top Layer w8: CN1.19@14667,2920 14722,2920 14947,3145 14947,3700 15057,3810 15057,4180.85 15236.85,4360.7 15236.85,4435 15261.85,4460 15531.15,4460 v2(15546.85,4475.7)
  Bottom Layer w8: v2@15541.85,4475.7 v2(15546.85,4475.7) 15726.85,4475.7 15757.8,4506.64 17273.64,4506.64 R53.1@17387,4620
LED_Y10: CN2.23 R58.1 | length 2992.5
  Top Layer w8: v2(10995.59,4700) 10995.59,4661.96 11107.55,4550 11844.8,4550 11872,4522.8 11872,2988 11990,2870 12217,2870 CN2.23@12267,2920
  Bottom Layer w12: R58.1@10974.59,4710 v2@10995.59,4710
MG_DM: CJ1.2 R86.1 | length 2194
  Top Layer w12: R86.1@14768.78,3267.23 14768.78,5188.03 cw(c14868.78,5188.03) 14798.07,5258.74 14853.15,5313.81 ccw(c14794.39,5372.57) 14877.48,5372.57 CJ1.2@14877.48,5424.1
MG_DP: CJ1.3 R84.1 | length 2195.8
  Top Layer w12: 14750.78,3266.47 14750.78,5195.48 cw(c14850.78,5195.48) 14780.07,5266.19 14842.24,5328.36 ccw(c14800.59,5370) 14859.48,5370 CJ1.3@14859.48,5424.1
MG_PA2: CN1.28 R90.2 | length 4210.7
  Top Layer w8: v9@15512,2375 15554.06,2375 15676.77,2497.7 15676.77,4588.8 15868.39,4780.42 15868.39,5398.61 R90.2@15867,5400
  Bottom Layer w8: CN1.28@14567,2520 14616.32,2470.68 14702,2470.68 14788.07,2384.61 15516.96,2384.61 v9(15521.77,2379.8)
MG_PA5: CN1.29 R107.2 | length 4574.2
  Top Layer w8: v9@15536.77,2300 15546.59,2300 15717.98,2471.39 15717.98,4571.73 15909.6,4763.35 15909.6,5284.32 16015.28,5390 16267,5390 R107.2@16347,5470
  Bottom Layer w8: CN1.29@14682.35,2404.8 14702.35,2404.8 ; CN1.29@14687.15,2420 14702.35,2404.8 ; 14702.49,2404.8 14702.35,2404.8 ; v9(15536.77,2309.8) 15512.35,2309.8 15462.54,2359.61 14747.54,2359.61 14702.35,2404.8
MG_PB0: CN2.40 R101.2 U3.1 | length 948.4
  Bottom Layer w8: CN2.40@12167,2120 12112,2065 12112,1995 12137,1970 12599.26,1970 12622,1992.74 12622,2062.74 12602,2082.74 R101.2@12583.22,2082.74 U3.1@12583.22,2171.26 12583.22,2106
MG_PB1: CN2.39 R130.1 U3.2 | length 4173
  Top Layer w8: v2(14367,2158.74) 14402,2123.74 14402,1654.77 14449.04,1607.74 v2@14602,1607.74
  Bottom Layer w8: CN2.39@12267,2120 12384.74,2237.74 12527,2237.74 ; U3.2@12533.22,2171.26 12533.22,2231.52 ; 14076.79,2157.74 13832,2157.74 ; v2@14357,2157.74 13832,2157.74 ; R130.1@14586,753.89 14577.15,762.74 14554.26,762.74 14535.6,781.4 14535.6,1121.34 14602,1187.74 v2@14602,1607.74 ; 12527,2237.74 12533.22,2231.52 ; 12527,2237.74 12539.44,2237.74 ; 12533.22,2231.52 12539.44,2237.74 ; 12539.44,2237.74 13177,2237.74 13207,2267.74 13597,2267.74 13707,2157.74 13832,2157.74
  other v2: 14607,1615.74
MG_PB2: CN2.38 R62.2 U1.3 U2.3 U3.6 U4.3 | length 13138.7
  Top Layer w8: v2(6940,688.48) v2(6940,949.89) ; v2@12076.85,824.62 12076.85,2129.85 CN2.38@12167,2220 ; v2(14506.6,1220) v2(14717,1220)
  Bottom Layer w8: U4.3@5094.02,1051.07 5041.18,1051.07 5020,1029.89 5020,856.47 5187.98,688.48 v2@6935,688.48 ; v2@6940,954.89 6940,1014.89 6976.18,1051.07 U2.3@7034.02,1051.07 ; v2@6945,678.48 7538.29,678.48 7553.29,693.48 10712.88,693.48 10835.87,816.47 v2(12085,816.47) 12126,816.47 12154.53,845 14444.07,845 14463.6,864.53 14463.6,1189.34 v2@14494.26,1220 ; CN2.38@12167,2220 12217,2270 12217,2445.48 12240,2468.48 12292,2468.48 12353.52,2530 12467,2530 12483.22,2513.78 U3.6@12483.22,2466.54 ; v2@14714.64,1222.36 R62.2@14714.64,1278.01 14737.51,1300.89 14829,1300.89 14840.43,1289.45 U1.3@14840.43,1234.89 U1.3@14840.43,1225.98
MG_PB3: CN2.37 R81.1 R109.2 U3.5 U4.2 | length 9697.9
  Top Layer w8: v2(7525,708.48) v2(7525,929.89) ; v2(12105,845.47) 12096.85,853.62 12096.85,2119.85 12142,2165 12192,2165 12247,2220 CN2.37@12267,2220
  Bottom Layer w8: U4.2@5094.02,1025.48 5045.59,1025.48 5040,1019.89 5040,863.47 5189.98,713.48 10704.6,713.48 10836.58,845.47 v2(12105,845.47) ; R81.1@7490,929.89 v2(7525,929.89) ; CN2.37@12267,2220 12281.7,2220 12434.44,2372.74 ; U3.5@12433.22,2466.54 12433.22,2373.96 12434.44,2372.74 ; R109.2@12667,2372.74 12434.44,2372.74
MG_PB4: CN2.32 R102.2 U3.7 | length 545
  Bottom Layer w8: CN2.32@12167,2520 12217,2570 12227,2570 ; 12297,2570 12227,2570 ; U3.7@12533.22,2466.54 12533.22,2543.78 R102.2@12527,2550 12507,2570 12227,2570
MG_PB5: CN2.31 R100.2 U3.3 | length 983
  Bottom Layer w8: CN2.31@12267,2520 12252,2520 12202,2470 12140.53,2470 12112,2441.47 12112,2196.47 12137,2171.47 12197,2171.47 12217,2151.47 12217,2095 12242,2070 12470.48,2070 R100.2@12483.22,2082.74 U3.3@12483.22,2171.26
MG_PB8: CN2.28 R129.2 | length 2883.4
  Top Layer w8: CN2.28@12167,2720 12217,2770 12307,2770 12337,2740 12337,2513.48 12293.52,2470 12076.85,2470 12056.85,2450 12056.85,805.15 12217,645 12442,645 12472,615 R129.2@12472,606.47
MG_PB9: CN2.27 R128.2 | length 2390.7
  Top Layer w8: CN2.27@12247,2720 CN2.27@12267,2720 ; R128.2@12252,606.47 12227.25,606.47 12036.85,796.87 12036.85,2544.85 12062,2570 12187,2570 12217,2600 12217,2655 CN2.27@12267,2705
MG_PC4: CN2.14 CN3.5 | length 4493.3
  Top Layer w8: v2(12487,3470) 12487,3152.57 12752,2887.57 12752,1680 12512,1440 12512,1235.94 12717,1030.94 12717,315 12762,270 13277,270 13332,325 13332,365 CN3.5@13337,370
  Bottom Layer w8: CN2.14@12167,3420 12190.53,3420 12240.53,3470 v2(12487,3470)
MG_PC5: CN2.13 CN3.3 | length 4030.8
  Top Layer w8: v2@12512,3420 12512,3157.57 12772.23,2897.34 12772.23,1606.88 12617,1451.65 12617,1166.3 12742,1041.3 12742,325 12772,295 13102,295 13132,325 13132,365 CN3.3@13137,370
  Bottom Layer w8: CN2.13@12267,3420 v2(12517,3420)
MG_PC6: CN2.12 R127.2 SW111.1 SW111.3 | length 4681.1
  Top Layer w10: SW111.1@10991,204.63 11059.85,273.48 11249.6,273.48 11269.13,253.95 R127.2@11269.13,242.92 ; SW111.3@10991,460.63 11041.92,460.63 11109.06,393.48 11265.48,393.48 11323.47,451.47 11477,451.47 11971.85,946.32 11971.85,2853.63 11842,2983.48 v2(11842,3360)
  Bottom Layer w8: v2(11842,3360) 11842,3365 11997,3520 CN2.12@12167,3520
  Bottom Layer w10: SW111.1@10991,204.63 SW111.3@10991,460.63
MG_PD4: CN1.14 R86.2 | length 263.2
  Top Layer w12: CN1.14@14567,3220 14587.71,3199.29 ccw(c14658.42,3270) 14640.35,3171.65 ccw(c14658.42,3270) 14658.42,3170 14718.72,3170 ccw(c14718.72,3238.28) 14767,3190 R86.2@14782.87,3205.87 ; R86.2@14782.87,3217.8 R86.2@14782.87,3205.87 ; R86.2@14787.87,3210.87 R86.2@14782.87,3205.87
MG_PD5: CN1.13 R84.2 | length 63.7
  Top Layer w12: CN1.13@14669.2,3217.8 R84.2@14732.87,3217.8
NetD1_1: D1.1 R1.2 | length 88
  Top Layer w20: R1.2@15097,5370 D1.1@15097,5458
NetD4_1: D4.1 SW1.1 | length 370
  Bottom Layer w8: SW1.1@332.08,5026.89 D4.1@702.08,5026.89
